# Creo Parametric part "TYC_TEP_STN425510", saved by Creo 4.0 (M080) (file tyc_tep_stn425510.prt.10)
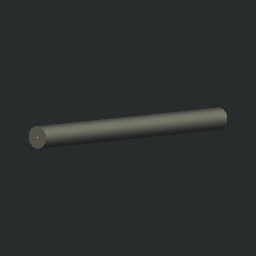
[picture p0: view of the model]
Units: Custom; MM, KILOGRAM, SECS
Materials in the file: OCEL_N

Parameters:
  NORMINFO = "Stabstahl Formstahl; Warmgewalzter rundkantiger U-Stahl"
  KATEGORIE = "0"
  DESIGNER = "."
  DATE = "."
  FORMAT = "."
  MOD_INDEX_1 = "."
  MOD_INDEX_2 = "."
  MOD_INDEX_3 = "."
  MOD_INDEX_4 = "."
  MOD_INDEX_5 = "."
  MOD_INDEX_6 = "."
  MOD_INDEX_7 = "."
  MOD_INDEX_8 = "."
  MOD_NOTE_1 = "."
  MOD_NOTE_2 = "."
  MOD_NOTE_3 = "."
  MOD_NOTE_4 = "."
  MOD_NOTE_5 = "."
  MOD_NOTE_6 = "."
  MOD_NOTE_7 = "."
  MOD_NOTE_8 = "."
  MOD_DATE_1 = "."
  MOD_DATE_2 = "."
  MOD_DATE_3 = "."
  MOD_DATE_4 = "."
  MOD_DATE_5 = "."
  MOD_DATE_6 = "."
  MOD_DATE_7 = "."
  MOD_DATE_8 = "."
  MOD_NAME_1 = "."
  MOD_NAME_2 = "."
  MOD_NAME_3 = "."
  MOD_NAME_4 = "."
  MOD_NAME_5 = "."
  MOD_NAME_6 = "."
  MOD_NAME_7 = "."
  MOD_NAME_8 = "."
  HERSTELLER = "."
  ZEICHNUNGSNUMMER = "."
  NAZOV = "TYC_TEP_STN425510"
  ROZMER = "KR 8x100"
  NORMA = "STN 42 5510"
  MATERIAL_ZAKL = "."
  HMOTNOST_HR = "."
  PTC_MATERIAL_NAME = "OCEL_N"

Other parameters: L, QUERSCHNITT, HMOTNOST, HUSTOTA, HMOTNOST_1, D24

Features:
  1. datum plane "Y-Y"
  2. datum plane "X-X"
  3. datum plane "Z-Z"
  4. coordinate system
  5. datum axis
  6. datum axis
  7. datum axis
  8. protrusion
  9. datum point "PNT0"
  10. datum point "PNT1"
  11. curve

Other named items: ZZ, XX, YY, CS0

Named dimensions: Laenge, laenge_nf

Layers: BEZUG, BEZUGSACHSEN, KONSTRUKTIONSELEMENTE, PLAZIERUNG, PROFIL_NEUTRALE_FASER

Notes: Rundstahl | Rund 8x100 | DxL 8x100 | Gewicht:  | 0.087 | Querschnittsfläche: A=  | 0.503 |  cm²

Family table entries: GENERIC, TYC_KR_6, TYC_TEP_STN425510, value(d_val), value(s_val), value(i_val), TYC_KR_7, TYC_TEP_STN425510, TYC_KR_8, TYC_TEP_STN425510, !/ , TYC_KR_10, TYC_TEP_STN425510, !/$, TYC_KR_12, TYC_TEP_STN425510, !/(, TYC_KR_13, TYC_TEP_STN425510, !/*, TYC_KR_14, TYC_TEP_STN425510, !/,, TYC_KR_15, TYC_TEP_STN425510, !/., TYC_KR_16, TYC_TEP_STN425510, !/0, TYC_KR_17, TYC_TEP_STN425510, !/1, TYC_KR_18, TYC_TEP_STN425510, !/2, TYC_KR_19, TYC_TEP_STN425510, !/3, TYC_KR_20, TYC_TEP_STN425510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

Surfaces: 2 plane, 1 cylinder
